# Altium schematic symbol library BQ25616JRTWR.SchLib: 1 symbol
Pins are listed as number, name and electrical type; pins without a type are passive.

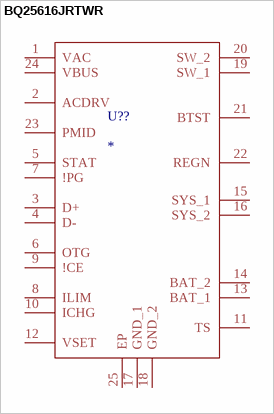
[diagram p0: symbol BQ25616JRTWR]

## BQ25616JRTWR
designator U??
footprint QFN50P400X400X80
pins: 1 VAC, 2 ACDRV, 3 D+, 4 D-, 5 STAT, 6 OTG, 7 !PG, 8 ILIM, 9 !CE, 10 ICHG, 11 TS, 12 VSET, 13 BAT_1, 14 BAT_2, 15 SYS_1, 16 SYS_2, 17 GND_1, 18 GND_2, 19 SW_1, 20 SW_2, 21 BTST, 22 REGN, 23 PMID, 24 VBUS, 25 EP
